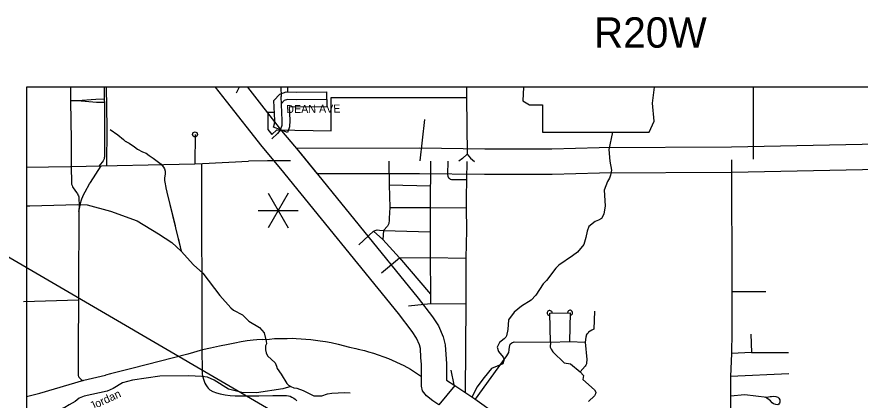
# Model space of a CAD drawing. Extents: x 19118 to 454486, y 1325406 to 1693506.
# Drawn here: x 24877 to 25720, y 1325997 to 1326380 of the extents above; entities that cross this region are included whole.
import ezdxf

# ---------------------------------------------------------------- set-up
doc = ezdxf.new("R2010")
doc.units = 0
for name, color, linetype in [('Default', 7, 'Continuous'), ('S_CURB', 7, 'Continuous'), ('S_PAVEMENT_CROWN', 7, 'Continuous')]:
    doc.layers.add(name, color=color, linetype=linetype)

msp = doc.modelspace()

# ---------------------------------------------------------------- linework, layer by layer
at = {"layer": 'Default'}
for p, q in [((25186.77, 1326305.12), (25186.94, 1326290.12)), ((25147.69, 1326264.64), (25133.62, 1326269.86)), ((25148.49, 1326203.89), (25128.49, 1326169.25)), ((25128.49, 1326203.89), (25148.49, 1326169.25)), ((25118.49, 1326186.57), (25158.49, 1326186.57))]:
    msp.add_line(p, q, dxfattribs=at)
for points in [[(24930.81, 1326309.74), (24931.05, 1326295.81), (24931.62, 1326256.72), (24931.62, 1326230.42)], [(24964.54, 1326309.74), (24964.54, 1326309.56), (24964.87, 1326282.01), (24964.87, 1326241.78), (24964.86, 1326240.26), (24964.76, 1326239.18), (24964.56, 1326238.25), (24964.29, 1326237.47), (24963.48, 1326236.13), (24962.45, 1326234.75), (24959.39, 1326231.03)], [(24967.16, 1326231.2), (24967.45, 1326269.08), (24967.07, 1326309.74)], [(25086.73, 1326295.94), (25075.82, 1326309.74)], [(25099.52, 1326309.74), (25096.53, 1326303.7)], [(25107.68, 1326309.74), (25141.89, 1326266.22), (25160.44, 1326244.1), (25278.36, 1326099.11), (25292.53, 1326080.16), (25298.69, 1326071.26), (25303.39, 1326060.19), (25305.3, 1326052.38), (25306.21, 1326038.14)], [(25141.21, 1326309.74), (25141.48, 1326300.68)], [(25147.61, 1326309.74), (25147.65, 1326305.17)], [(25326.56, 1326309.74), (25326.64, 1326299.68), (25327.23, 1326242.82)], [(25383.44, 1326309.74), (25382.85, 1326296.28), (25389.61, 1326292.05), (25402.3, 1326292.05), (25402.3, 1326264.98), (25508.89, 1326264.98), (25513.96, 1326275.98), (25512.27, 1326293.74), (25514.27, 1326309.74)], [(25612.77, 1326309.74), (25612.88, 1326237.98)], [(24964.69, 1326297.84), (24956.27, 1326297.53), (24937.93, 1326296.1)], [(25132.16, 1326262.4), (25136.97, 1326267.32), (25191.28, 1326266.21), (25191.48, 1326299.69), (25326.64, 1326299.68)], [(25134.13, 1326296.69), (25140.19, 1326302.88), (25146.51, 1326305.22), (25157.14, 1326304.79), (25186.77, 1326305.12)], [(25140.66, 1326267.25), (25142.32, 1326271.74), (25142.45, 1326276.63), (25141.48, 1326300.68)], [(25186.85, 1326297.62), (25157.03, 1326297.28), (25147.7, 1326297.66), (25144.37, 1326296.43), (25141.64, 1326293.64)], [(24937.93, 1326296.1), (24931.05, 1326296.1)], [(24964.73, 1326294.66), (24956.84, 1326294.66), (24937.93, 1326296.1)], [(25281.07, 1326039.63), (25280.49, 1326048.58), (25279.58, 1326052.29), (25276.67, 1326059.14), (25272.23, 1326065.56), (25258.65, 1326083.73), (25141.16, 1326228.18), (25122.48, 1326250.46), (25086.73, 1326295.94)], [(25133.62, 1326269.86), (25134.86, 1326273.18), (25134.94, 1326276.58), (25134.13, 1326296.69)], [(25149.41, 1326290.09), (25149.95, 1326276.69), (25149.78, 1326270.29), (25147.69, 1326264.64)], [(25186.94, 1326290.12), (25156.92, 1326289.78), (25149.41, 1326290.09)], [(25134.62, 1326284.67), (25128.15, 1326284.66), (25128.05, 1326267.57)], [(25284.68, 1326277.67), (25279.85, 1326236.22)], [(24970.65, 1326267.42), (24978.17, 1326262.22), (24983.85, 1326257.53), (24985.69, 1326256.02), (24989.54, 1326254.01), (24994.88, 1326250.32), (24997.73, 1326247.97), (25002.74, 1326245.29), (25006.42, 1326243.78), (25009.43, 1326241.44), (25013.61, 1326238.92), (25017.45, 1326235.9), (25021.46, 1326232.89), (25023.8, 1326229.87), (25024.81, 1326228.36), (25025.64, 1326225.84), (25025.64, 1326222.83), (25024.81, 1326219.31), (25024.81, 1326216.62), (25025.48, 1326213.27), (25026.31, 1326209.25), (25027.33, 1326204.97)], [(24970.65, 1326267.42), (24978.17, 1326262.22), (24983.85, 1326257.53), (24985.69, 1326256.02), (24986.49, 1326255.6)], [(25128.05, 1326267.57), (25132.16, 1326262.4)], [(25140.66, 1326267.25), (25137.71, 1326263.54), (25132.19, 1326258.34)], [(25472.49, 1326264.98), (25468.57, 1326247.49), (25469.59, 1326235.91), (25471.31, 1326226.85), (25470.48, 1326222.01), (25469.3, 1326218.76), (25467.51, 1326215.69), (25463.91, 1326206.95), (25464.97, 1326191.35), (25463.78, 1326182.79), (25461.42, 1326178.6), (25458.28, 1326176.79), (25454.92, 1326175.57), (25448.69, 1326170.64), (25446.96, 1326165.77), (25445.78, 1326159.52), (25443.63, 1326152.53), (25437.39, 1326145.09), (25432.42, 1326141.21)], [(25055.35, 1326262.67), (25055.08, 1326233.12)], [(26082.36, 1326228.48), (26080.78, 1326253.49), (25864.96, 1326254.95), (25721.7, 1326252.67), (25591.11, 1326249.83), (25459.05, 1326249.15), (25411.66, 1326247.9), (25344.74, 1326247.77), (25279.94, 1326248.72), (25156.75, 1326248.64), (25177.07, 1326223.66)], [(24997.41, 1326248.24), (24997.73, 1326247.97), (25002.74, 1326245.29), (25006.42, 1326243.78), (25009.43, 1326241.44), (25013.61, 1326238.92), (25017.45, 1326235.9), (25021.46, 1326232.89), (25023.8, 1326229.87), (25024.81, 1326228.36), (25025.64, 1326225.84), (25025.64, 1326223.21)], [(25327.23, 1326242.82), (25322.45, 1326238.54), (25319.05, 1326235.82)], [(25327.23, 1326242.82), (25330.5, 1326238.73), (25334.46, 1326235.51)], [(24887.1, 1326229.76), (24931.04, 1326230.41), (25055.08, 1326233.12), (25062.67, 1326233.69)], [(24931.62, 1326230.42), (24931.98, 1326214.18), (24932, 1326213.46), (24932.12, 1326212.76), (24932.26, 1326212.16), (24932.54, 1326211.41), (24933.02, 1326210.4), (24933.73, 1326209.24), (24937.05, 1326204.45), (24937.84, 1326203.25), (24938.43, 1326202.2), (24938.84, 1326201.19), (24939.14, 1326200.11), (24939.35, 1326198.91), (24939.42, 1326197.71), (24939.5, 1326192.92), (24939.26, 1326184.86), (24939.26, 1326169.01), (24939, 1326124.3), (24938.48, 1326023.44), (24938.55, 1326022.39), (24938.68, 1326021.62), (24938.86, 1326021.05), (24939.06, 1326020.6), (24939.31, 1326020.15), (24939.58, 1326019.74), (24939.93, 1326019.32), (24940.28, 1326018.95), (24940.57, 1326018.65), (24940.91, 1326018.35), (24941.78, 1326017.68), (24942.63, 1326017.12), (24943.48, 1326016.58)], [(24939.28, 1326185.57), (24941.72, 1326196.11), (24942.4, 1326198.33), (24943.33, 1326200.63), (24944.27, 1326203.02), (24945.55, 1326205.41), (24949.97, 1326213.26), (24950.82, 1326214.71), (24961.73, 1326231.08)], [(25061.92, 1326233.06), (25062.22, 1326047.06)], [(25062.67, 1326233.69), (25108.66, 1326235.88)], [(25150.8, 1326236.14), (25127.77, 1326236.24), (25108.66, 1326235.88)], [(25177.07, 1326223.66), (25279.76, 1326223.72), (25344.58, 1326222.77), (25412.01, 1326222.9), (25459.45, 1326224.15), (25591.45, 1326224.83), (25722.17, 1326227.68), (25865.08, 1326229.95), (26082.36, 1326228.48)], [(25249.03, 1326235.95), (25249.28, 1326212.11), (25249.98, 1326189.48), (25249.36, 1326178.84), (25249.23, 1326176.83), (25248.96, 1326173.52), (25247.6, 1326170.83), (25243.8, 1326166.52), (25242.92, 1326157.47)], [(25290.68, 1326235.89), (25290.33, 1326189.48), (25290.19, 1326165.43), (25290.41, 1326139.58), (25290.52, 1326103.01), (25290.45, 1326093.58)], [(25307.9, 1326235.79), (25307.67, 1326222.56), (25307.93, 1326220.86), (25308.69, 1326219.28), (25309.12, 1326218.81), (25310.12, 1326217.95), (25310.55, 1326217.75), (25311.56, 1326217.48), (25326.38, 1326217.49)], [(25327.03, 1326235.56), (25326.38, 1326217.49), (25326.21, 1326199.65), (25326.18, 1326189.23), (25326.38, 1326166.79), (25325.98, 1326138.81), (25325.8, 1326093.41), (25325.26, 1326004.79)], [(25591.28, 1326237.33), (25591.49, 1326105.26)], [(25026.11, 1326210.23), (25026.31, 1326209.25), (25027.33, 1326204.97), (25035.4, 1326171.74)], [(25027.33, 1326204.97), (25041.66, 1326145.99)], [(25249.28, 1326212.11), (25290.49, 1326211.17)], [(24887.1, 1326191.26), (24890.37, 1326191.26), (24938.41, 1326192.48), (24947.73, 1326192.25)], [(24947.73, 1326192.25), (24971.08, 1326185.8), (24997.54, 1326176.25), (25018.93, 1326163.37), (25032.1, 1326154.74), (25041.66, 1326145.99), (25053.96, 1326132.45)], [(25249.98, 1326189.48), (25290.33, 1326189.48), (25326.18, 1326189.23)], [(25219.07, 1326152.43), (25233.81, 1326165.87), (25235.28, 1326166.72), (25237.31, 1326167.12), (25239.67, 1326167.08), (25243.8, 1326166.52), (25290.19, 1326165.43)], [(25233.81, 1326165.87), (25242.92, 1326157.47), (25259.49, 1326139.21), (25290.52, 1326103.01)], [(25038.52, 1326158.91), (25041.66, 1326145.99)], [(25241.6, 1326124.35), (25259.49, 1326139.21), (25290.41, 1326139.58), (25325.98, 1326138.81)], [(25432.42, 1326141.21), (25418.74, 1326131.82), (25415.83, 1326129.11), (25406.46, 1326116.76), (25403.18, 1326113.24), (25395.78, 1326101.96), (25391.15, 1326097.09), (25381.65, 1326090.94), (25374.16, 1326084.97), (25368.43, 1326077.16), (25367.67, 1326067.51), (25366.39, 1326061.35), (25365.75, 1326059.83), (25364.1, 1326058.17), (25359.52, 1326054.8), (25357.28, 1326050.11), (25358.54, 1326045.75), (25363.15, 1326039.99), (25363.81, 1326038.31), (25363.86, 1326036.81), (25362.99, 1326033.37)], [(25053.96, 1326132.45), (25063.32, 1326124.09), (25080.29, 1326101.67), (25091.18, 1326089.32), (25093.9, 1326086.93), (25102.64, 1326082.24)], [(25625.63, 1326105.25), (25591.49, 1326105.26)], [(25591.49, 1326105.26), (25591.53, 1326065.06)], [(25591.49, 1326105.26), (25591.53, 1326065.06)], [(24883.91, 1326095.78), (24938.86, 1326097.31)], [(25268.5, 1326091.42), (25290.45, 1326093.58), (25325.8, 1326093.41)], [(25102.64, 1326082.24), (25109.17, 1326075.95), (25119.7, 1326069.71), (25124.3, 1326064.35), (25126.52, 1326056.14), (25126.7, 1326053.32), (25125.87, 1326051.18), (25125.8, 1326047.47), (25126.32, 1326044.28), (25127.92, 1326041.43), (25135.28, 1326034.37), (25136.9, 1326031.12), (25137.29, 1326028.53)], [(25410.45, 1326055.04), (25409.68, 1326084.1), (25429.99, 1326084.36), (25429.34, 1326055.57)], [(25454.36, 1326086.01), (25453.67, 1326068.15), (25451.7, 1326066.9), (25450.02, 1326065.96), (25448.54, 1326064.83), (25447.67, 1326063.8), (25446.88, 1326062.98), (25446.21, 1326061.97), (25445.93, 1326061.06), (25445.65, 1326059.95), (25445.17, 1326054.83), (25446.67, 1326037.52), (25446.55, 1326034.01), (25446.36, 1326033.5), (25445.79, 1326031.98), (25445.11, 1326030.97), (25440.24, 1326025.24), (25443.52, 1326021.81), (25442.71, 1326017.78), (25454.36, 1326007.32), (25455.61, 1326005.14), (25455.45, 1326003.43), (25454.49, 1326001.51), (25448.32, 1325995.55)], [(25591.53, 1326065.06), (25591.38, 1326043.83)], [(25610.52, 1326063.13), (25611.08, 1326044.61), (25591.38, 1326043.83)], [(25123.24, 1326057.7), (25117.06, 1326057.29), (25113.47, 1326056.99), (25107.61, 1326056.33), (25101.53, 1326055.38), (25095.04, 1326054.13), (25088.59, 1326052.81), (25079.95, 1326051.04), (25070.71, 1326049.13), (25062.8, 1326047.22), (25048.29, 1326043.11), (24992.16, 1326028.78), (24971.06, 1326023.49), (24966.09, 1326021.96)], [(25123.24, 1326057.7), (25129.63, 1326058.13), (25134.62, 1326058.6), (25141.82, 1326058.65), (25147.53, 1326058.75), (25152.63, 1326058.83), (25156.34, 1326058.75), (25171.19, 1326057.77), (25180.45, 1326056.49), (25185.69, 1326055.57), (25191.43, 1326054.56), (25198.49, 1326053.01), (25209.82, 1326049.89), (25216.07, 1326048.61), (25218.39, 1326048.09), (25224.75, 1326046.5), (25228.7, 1326045.44), (25233.61, 1326044), (25248.67, 1326038.54), (25263.92, 1326031.83)], [(25335.38, 1325998.03), (25366.93, 1326041.43), (25368.86, 1326044.58), (25369.1, 1326047.49), (25369.18, 1326048.1), (25369.71, 1326051.52), (25370.18, 1326052.83), (25371.74, 1326054.47), (25374.32, 1326055.33), (25410.45, 1326055.04), (25429.34, 1326055.57), (25445.17, 1326054.83)], [(25410.45, 1326055.04), (25410.06, 1326050.02), (25411.11, 1326047.84), (25412.67, 1326045.47), (25412.98, 1326045.08), (25424.13, 1326034.2), (25430.45, 1326033.34), (25440.24, 1326025.24)], [(25062.22, 1326047.06), (25062.45, 1326026.92), (25062.63, 1326023), (25063.1, 1326020.39), (25063.69, 1326018.01), (25064.4, 1326015.99), (25065.12, 1326014.09), (25066.06, 1326012.19), (25067.43, 1326010.29), (25068.61, 1326008.86), (25070.21, 1326007.44), (25073.29, 1326005.77), (25076.73, 1326004.47), (25080.52, 1326003.4), (25085.49, 1326002.33), (25090.35, 1326001.73), (25095.56, 1326001.38), (25102.02, 1326001.26), (25107.94, 1326001.26), (25119.26, 1326001.38), (25133.12, 1326001.62), (25141.3, 1326001.85), (25146.86, 1326001.62), (25148.88, 1326001.38), (25150.54, 1326000.9), (25152.2, 1326000.19), (25153.97, 1325999.12), (25155.39, 1325997.93), (25157.05, 1325996.27)], [(25611.08, 1326044.61), (25648.12, 1326044.6)], [(25286.44, 1326001.46), (25282.59, 1326006.49), (25281.73, 1326011.11), (25281.52, 1326032.62), (25281.07, 1326039.63)], [(25306.21, 1326038.14), (25306.51, 1326033.54), (25306.67, 1326017.16)], [(25591.38, 1326043.83), (25590.42, 1326020.81), (25590.37, 1326001.26), (25590.13, 1325985.22), (25589.65, 1325975.89), (25589.18, 1325969.96), (25587.38, 1325956.69), (25579.38, 1325908.49), (25571.02, 1325853.97), (25567.09, 1325829.89)], [(25137.29, 1326028.53), (25141.43, 1326023.11), (25147.15, 1326013.61), (25148.89, 1326012.15), (25151.22, 1326010.6), (25154.15, 1326009.46), (25157.06, 1326009.03), (25163.42, 1326006.56), (25174.04, 1326001.39), (25181.95, 1326001.37), (25187.61, 1326003.3), (25192.09, 1326004.1), (25204.79, 1326004.69), (25210.29, 1326004.31)], [(25263.92, 1326031.83), (25270.5, 1326028.06), (25277.7, 1326023.25), (25281.7, 1326020.59)], [(25362.99, 1326033.37), (25351.62, 1326028.66), (25344.12, 1326019.76), (25336.93, 1326010.18), (25332.11, 1326000.23)], [(24944.4, 1326016.85), (24966.09, 1326021.96)], [(25151.22, 1326010.6), (25142.96, 1326008.4), (25116.69, 1326004.47), (25102.28, 1326004.56), (25088.66, 1326007.98), (25074.64, 1326017), (25067.94, 1326019.87), (25062.21, 1326020.76), (25048.69, 1326021.19), (25020.18, 1326021.08), (24992.81, 1326017.11), (24982.99, 1326014.46), (24973.69, 1326008.73), (24967.48, 1326006.01)], [(25310.91, 1326027.08), (25313.87, 1326012.37)], [(25648.59, 1326023.43), (25590.42, 1326020.81)], [(24887.1, 1326000.66), (24900.33, 1326003.93), (24944.4, 1326016.85)], [(25314.93, 1326011.67), (25298.95, 1325992.27), (25292.97, 1325996.25), (25286.44, 1326001.46)], [(25306.67, 1326017.16), (25314.93, 1326011.67)], [(25314.93, 1326011.67), (25334.96, 1325998.33), (25357.18, 1325982.47)], [(24967.48, 1326006.01), (24944.74, 1326001.02), (24939.53, 1325998.93), (24935.62, 1325995.79), (24929.62, 1325992.38), (24925.45, 1325989.77), (24921.53, 1325988.46), (24916.84, 1325987.67), (24891.8, 1325986.89), (24888.41, 1325986.36), (24887.1, 1325985.81)], [(25590.37, 1326001.26), (25604.74, 1326002.69), (25626.42, 1325999.97), (25629.81, 1326000.55), (25631.3, 1326000.79), (25633.2, 1326001.03), (25635.6, 1326000.78), (25637.42, 1326000.02), (25638.64, 1325999.15), (25639.58, 1325997.36), (25639.64, 1325995.06), (25639.36, 1325993.95), (25638.38, 1325992.93), (25637.49, 1325992.5), (25635.69, 1325992.56), (25633.27, 1325993.41), (25631.85, 1325994.38), (25630.1, 1325996.25), (25625.12, 1325999.94)]]:
    msp.add_lwpolyline(points, dxfattribs=at)
msp.add_circle((25055.35, 1326262.67), 2.5, dxfattribs=at)
for centre, start, end in [((25409.68, 1326084.1), 0.72741, 271.50474), ((25429.99, 1326084.37), 268.69576, 179.28369)]:
    msp.add_arc(centre, 2.5, start, end, dxfattribs=at)
at = {"layer": 'S_CURB'}
msp.add_lwpolyline([(26142.72, 1326309.74), (24887.1, 1326309.74), (24887.1, 1325684.11), (26142.72, 1325684.11)], close=True, dxfattribs=at)
at = {"layer": 'S_PAVEMENT_CROWN'}
msp.add_lwpolyline([(25402.73, 1325828.09), (24751.06, 1326208.5)], dxfattribs=at)

# ---------------------------------------------------------------- texts
at = {"layer": 'Default'}
for s, rotation, p in [('DEAN AVE', 0.64568, (25146.57, 1326283.88)), ('Jordan', 24.91033, (24952.51, 1325986.93))]:
    msp.add_text(s, height=8, rotation=rotation, dxfattribs=at).set_placement(p)
at = {"layer": 'S_CURB'}
msp.add_text('R20W', height=30.36, dxfattribs=at).set_placement((25453.75, 1326349.31))

doc.saveas('drawing.dxf')
